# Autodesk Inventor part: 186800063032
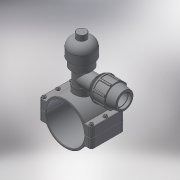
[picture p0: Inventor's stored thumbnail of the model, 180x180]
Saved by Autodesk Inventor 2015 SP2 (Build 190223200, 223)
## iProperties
Created: 2017-05
Part Number: 186800063032
Material: Generic
Description: PLASSON MECHANICAL TAPPING VALVE 63-32
Document SubType Name: Modeling
Designer: KIM
Density: 1 g/cm^3
Appearance: Default
Author: KIM
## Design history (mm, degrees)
derived "18680.ipt"
feature "Solid1::18680.ipt"
feature "Solid2::18680.ipt"
tag "TaggingFeature1"
body "Solid1"
other parameters: "d0" = 78.75, "d1" = 116, "d2" = 31.5, "d3" = 63, "d4" = 84, "d5" = 0, "d6" = 5.8, "d7" = 116, "d8" = 0.1, "d10" = 0, "d11" = 0.63, "d14" = 50.6376, "d20" = 0.63, "d23" = 0.63, "d37" = 8, "d38" = 39.5, "d39" = 0, "d40" = 3, "d41" = 5, "d42" = 0, "d43" = 6, "d44" = 3, "d45" = 0, "d46" = 0.63, "d51" = 66, "d52" = 38.952, "d53" = 25, "d54" = 0, "d55" = 32, "d57" = 0, "d58" = 68.04, "d60" = 0, "d63" = 8, "d66" = 68, "d67" = 32, "d68" = 11.25, "d69" = 27, "d70" = 64, "d71" = 48, "d72" = 1.92857, "d73" = 51.2, "d74" = 120 deg, "d75" = 48, "d76" = 10 deg, "d77" = 57.6, "d78" = 40.5, "d79" = 67, "d80" = 25.6, "d81" = 135, "d82" = 6.7, "d87" = 19.28571, "d90" = 59.52, "d91" = 35 deg, "d92" = 17.5 deg, "d94" = 0, "d96" = 360 deg, "d98" = 0.64, "d99" = 73.7, "d100" = 38.4, "d101" = 135 deg, "d102" = 1.28, "d105" = 3.2, "d106" = 0, "d107" = 0.1, "d109" = 50.6376, "d112" = 34.28571, "d113" = 4.5, "d116" = 0, "d121" = 46.7424, "d122" = 77.904, "d123" = 66.2184, "d124" = 45 deg, "d125" = 216, "d127" = 144, "d128" = 1, "d129" = 55, "d_" = 63, "B_" = 32, "G_" = 38.952, "A_" = 66, "L_" = 116, "L_1" = 84, "l_2" = 25, "d_1" = 32, "E_" = 64, "l_" = 67, "H_" = 135, "H_1" = 55
